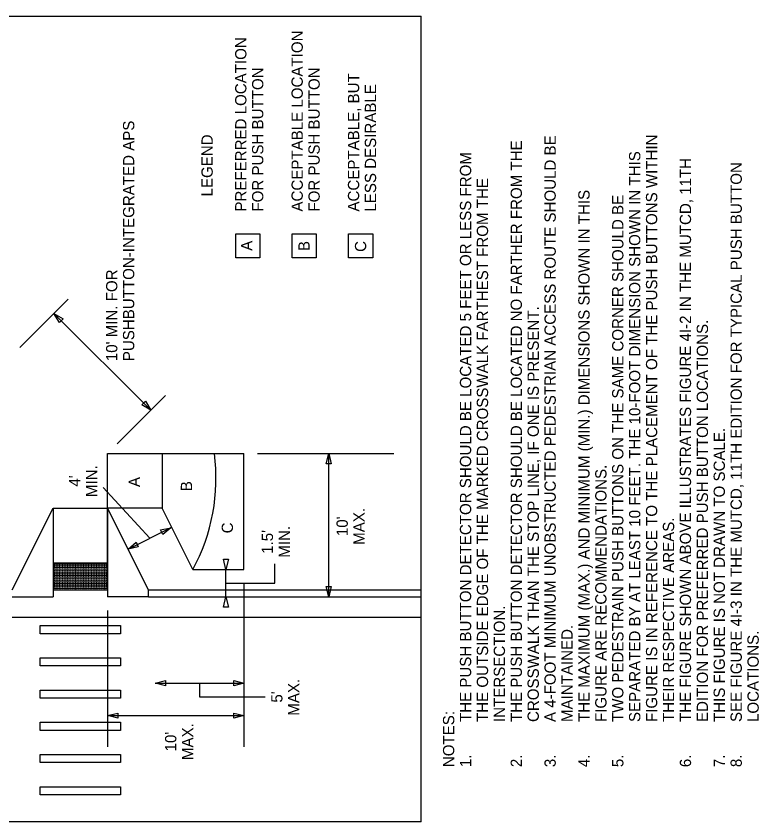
# Model space of a CAD drawing. Extents: x 610558 to 611161, y 419194 to 420064.
# Drawn here: x 610812 to 611088.7, y 419194 to 419494 of the extents above; entities that cross this region are included whole.
import ezdxf

# ---------------------------------------------------------------- set-up
doc = ezdxf.new("R2010")
doc.units = 0
doc.layers.add('Level 10', color=7, linetype='Continuous')

msp = doc.modelspace()

# ---------------------------------------------------------------- linework, layer by layer
at = {"layer": 'Level 10'}
for p, q in [((610673.08, 419494.01), (610962.92, 419494.01)), ((610962.92, 419194.01), (610962.92, 419494.01)), ((610813.45, 419370.66), (610831.4, 419388.61)), ((610826.14, 419383.35), (610862.24, 419347.26)), ((610849.73, 419334.74), (610867.68, 419352.7)), ((610866.43, 419331.13), (610896.9, 419331.13)), ((610896.9, 419287.96), (610896.9, 419331.13)), ((610901.98, 419331.13), (610952.77, 419331.13)), ((610928.49, 419277.81), (610928.49, 419331.13)), ((610861.86, 419299.65), (610844.51, 419318.55)), ((610810.56, 419280.35), (610825.8, 419310.82)), ((610825.8, 419310.82), (610846.11, 419310.82)), ((610825.8, 419310.82), (610825.8, 419280.35)), ((610825.8, 419310.82), (610825.8, 419277.81)), ((610846.11, 419280.35), (610846.11, 419310.82)), ((610861.35, 419280.35), (610846.11, 419310.82)), ((610846.11, 419310.82), (610846.11, 419277.81)), ((610877.86, 419287.96), (610866.43, 419310.82)), ((610853.73, 419295.58), (610869.98, 419303.71)), ((610825.8, 419290.5), (610846.11, 419290.5)), ((610877.86, 419287.96), (610896.9, 419287.96)), ((610890.19, 419277.81), (610890.19, 419287.96)), ((610825.8, 419280.35), (610846.11, 419280.35)), ((610861.35, 419277.81), (610861.35, 419280.35)), ((610861.35, 419280.35), (610962.92, 419280.35)), ((610896.9, 419282.89), (610896.9, 419221.94)), ((610810.56, 419277.81), (610825.8, 419277.81)), ((610861.35, 419277.81), (610846.11, 419277.81)), ((610861.35, 419277.81), (610962.92, 419277.81)), ((610846.11, 419272.73), (610846.11, 419221.94)), ((610810.56, 419270.19), (610861.35, 419270.19)), ((610861.35, 419270.19), (610962.92, 419270.19)), ((610863.89, 419245.65), (610896.9, 419245.65)), ((610846.11, 419233.56), (610896.9, 419233.56)), ((610962.92, 419194.01), (610673.08, 419194.01))]:
    msp.add_line(p, q, dxfattribs=at)
for points in [[(610893.85, 419403.96), (610893.85, 419412.96), (610902.85, 419412.96), (610902.85, 419403.96)], [(610914.85, 419403.96), (610914.85, 419412.96), (610923.85, 419412.96), (610923.85, 419403.96)], [(610935.85, 419403.96), (610935.85, 419412.96), (610944.85, 419412.96), (610944.85, 419403.96)], [(610828.16, 419379.99), (610826.14, 419383.35), (610829.51, 419381.33)], [(610860.22, 419350.63), (610862.24, 419347.26), (610858.87, 419349.28)], [(610846.11, 419310.82), (610846.11, 419331.13), (610866.43, 419331.13), (610866.43, 419310.82)], [(610927.54, 419327.32), (610928.49, 419331.13), (610929.44, 419327.32)], [(610865.82, 419302.69), (610869.65, 419303.54), (610866.67, 419300.99)], [(610857.56, 419296.43), (610853.73, 419295.58), (610856.71, 419298.14)], [(610891.14, 419291.77), (610890.19, 419287.96), (610889.24, 419291.77)], [(610929.44, 419281.62), (610928.49, 419277.81), (610927.54, 419281.62)], [(610889.24, 419274), (610890.19, 419277.81), (610891.14, 419274)], [(610820.96, 419264.08), (610820.96, 419267.08), (610850.96, 419267.08), (610850.96, 419264.08)], [(610820.96, 419252.08), (610820.96, 419255.08), (610850.96, 419255.08), (610850.96, 419252.08)], [(610867.7, 419244.7), (610863.89, 419245.65), (610867.7, 419246.61)], [(610893.09, 419246.61), (610896.9, 419245.65), (610893.09, 419244.7)], [(610820.96, 419240.08), (610820.96, 419243.08), (610850.96, 419243.08), (610850.96, 419240.08)], [(610849.92, 419232.61), (610846.11, 419233.56), (610849.92, 419234.51)], [(610893.09, 419234.51), (610896.9, 419233.56), (610893.09, 419232.61)], [(610820.96, 419228.08), (610820.96, 419231.08), (610850.96, 419231.08), (610850.96, 419228.08)], [(610820.96, 419216.08), (610820.96, 419219.08), (610850.96, 419219.08), (610850.96, 419216.08)], [(610820.96, 419204.08), (610820.96, 419207.08), (610850.96, 419207.08), (610850.96, 419204.08)]]:
    msp.add_lwpolyline(points, close=True, dxfattribs=at)
for points in [[(610890.19, 419282.89), (610908.43, 419282.89), (610908.43, 419290.07)], [(610880.39, 419245.65), (610880.39, 419240.57), (610904.82, 419240.57)]]:
    msp.add_lwpolyline(points, dxfattribs=at)
for centre in [(610826.36, 419289.95), (610826.36, 419289.35), (610826.96, 419289.95), (610826.96, 419289.35), (610827.56, 419289.95), (610827.56, 419289.35), (610828.16, 419289.95), (610828.16, 419289.35), (610828.76, 419289.95), (610828.76, 419289.35), (610829.36, 419289.95), (610829.36, 419289.35), (610829.96, 419289.95), (610829.96, 419289.35), (610830.56, 419289.95), (610830.56, 419289.35), (610831.16, 419289.95), (610831.16, 419289.35), (610831.76, 419289.95), (610831.76, 419289.35), (610832.36, 419289.95), (610832.36, 419289.35), (610832.96, 419289.95), (610832.96, 419289.35), (610833.56, 419289.95), (610833.56, 419289.35), (610834.16, 419289.95), (610834.16, 419289.35), (610834.76, 419289.95), (610834.76, 419289.35), (610835.36, 419289.95), (610835.36, 419289.35), (610835.96, 419289.95), (610835.96, 419289.35), (610836.56, 419289.95), (610836.56, 419289.35), (610837.16, 419289.95), (610837.16, 419289.35), (610837.76, 419289.95), (610837.76, 419289.35), (610838.36, 419289.95), (610838.36, 419289.35), (610838.96, 419289.95), (610838.96, 419289.35), (610839.56, 419289.95), (610839.56, 419289.35), (610840.16, 419289.95), (610840.16, 419289.35), (610840.76, 419289.95), (610840.76, 419289.35), (610841.36, 419289.95), (610841.36, 419289.35), (610841.96, 419289.95), (610841.96, 419289.35), (610842.56, 419289.95), (610842.56, 419289.35), (610843.16, 419289.95), (610843.16, 419289.35), (610843.76, 419289.95), (610843.76, 419289.35), (610844.36, 419289.95), (610844.36, 419289.35), (610844.96, 419289.95), (610844.96, 419289.35), (610845.56, 419289.95), (610845.56, 419289.35), (610826.36, 419288.75), (610826.36, 419288.15), (610826.36, 419287.55), (610826.36, 419286.95), (610826.36, 419286.35), (610826.96, 419288.75), (610826.96, 419288.15), (610826.96, 419287.55), (610826.96, 419286.95), (610826.96, 419286.35), (610827.56, 419288.75), (610827.56, 419288.15), (610827.56, 419287.55), (610827.56, 419286.95), (610827.56, 419286.35), (610828.16, 419288.75), (610828.16, 419288.15), (610828.16, 419287.55), (610828.16, 419286.95), (610828.16, 419286.35), (610828.76, 419288.75), (610828.76, 419288.15), (610828.76, 419287.55), (610828.76, 419286.95), (610828.76, 419286.35), (610829.36, 419288.75), (610829.36, 419288.15), (610829.36, 419287.55), (610829.36, 419286.95), (610829.36, 419286.35), (610829.96, 419288.75), (610829.96, 419288.15), (610829.96, 419287.55), (610829.96, 419286.95), (610829.96, 419286.35), (610830.56, 419288.75), (610830.56, 419288.15), (610830.56, 419287.55), (610830.56, 419286.95), (610830.56, 419286.35), (610831.16, 419288.75), (610831.16, 419288.15), (610831.16, 419287.55), (610831.16, 419286.95), (610831.16, 419286.35), (610831.76, 419288.75), (610831.76, 419288.15), (610831.76, 419287.55), (610831.76, 419286.95), (610831.76, 419286.35), (610832.36, 419288.75), (610832.36, 419288.15), (610832.36, 419287.55), (610832.36, 419286.95), (610832.36, 419286.35), (610832.96, 419288.75), (610832.96, 419288.15), (610832.96, 419287.55), (610832.96, 419286.95), (610832.96, 419286.35), (610833.56, 419288.75), (610833.56, 419288.15), (610833.56, 419287.55), (610833.56, 419286.95), (610833.56, 419286.35), (610834.16, 419288.75), (610834.16, 419288.15), (610834.16, 419287.55), (610834.16, 419286.95), (610834.16, 419286.35), (610834.76, 419288.75), (610834.76, 419288.15), (610834.76, 419287.55), (610834.76, 419286.95), (610834.76, 419286.35), (610835.36, 419288.75), (610835.36, 419288.15), (610835.36, 419287.55), (610835.36, 419286.95), (610835.36, 419286.35), (610835.96, 419288.75), (610835.96, 419288.15), (610835.96, 419287.55), (610835.96, 419286.95), (610835.96, 419286.35), (610836.56, 419288.75), (610836.56, 419288.15), (610836.56, 419287.55), (610836.56, 419286.95), (610836.56, 419286.35), (610837.16, 419288.75), (610837.16, 419288.15), (610837.16, 419287.55), (610837.16, 419286.95), (610837.16, 419286.35), (610837.76, 419288.75), (610837.76, 419288.15), (610837.76, 419287.55), (610837.76, 419286.95), (610837.76, 419286.35), (610838.36, 419288.75), (610838.36, 419288.15), (610838.36, 419287.55), (610838.36, 419286.95), (610838.36, 419286.35), (610838.96, 419288.75), (610838.96, 419288.15), (610838.96, 419287.55), (610838.96, 419286.95), (610838.96, 419286.35), (610839.56, 419288.75), (610839.56, 419288.15), (610839.56, 419287.55), (610839.56, 419286.95), (610839.56, 419286.35), (610840.16, 419288.75), (610840.16, 419288.15), (610840.16, 419287.55), (610840.16, 419286.95), (610840.16, 419286.35), (610840.76, 419288.75), (610840.76, 419288.15), (610840.76, 419287.55), (610840.76, 419286.95), (610840.76, 419286.35), (610841.36, 419288.75), (610841.36, 419288.15), (610841.36, 419287.55), (610841.36, 419286.95), (610841.36, 419286.35), (610841.96, 419288.75), (610841.96, 419288.15), (610841.96, 419287.55), (610841.96, 419286.95), (610841.96, 419286.35), (610842.56, 419288.75), (610842.56, 419288.15), (610842.56, 419287.55), (610842.56, 419286.95), (610842.56, 419286.35), (610843.16, 419288.75), (610843.16, 419288.15), (610843.16, 419287.55), (610843.16, 419286.95), (610843.16, 419286.35), (610843.76, 419288.75), (610843.76, 419288.15), (610843.76, 419287.55), (610843.76, 419286.95), (610843.76, 419286.35), (610844.36, 419288.75), (610844.36, 419288.15), (610844.36, 419287.55), (610844.36, 419286.95), (610844.36, 419286.35), (610844.96, 419288.75), (610844.96, 419288.15), (610844.96, 419287.55), (610844.96, 419286.95), (610844.96, 419286.35), (610845.56, 419288.75), (610845.56, 419288.15), (610845.56, 419287.55), (610845.56, 419286.95), (610845.56, 419286.35), (610826.36, 419285.75), (610826.36, 419285.15), (610826.36, 419284.55), (610826.36, 419283.95), (610826.36, 419283.35), (610826.96, 419285.75), (610826.96, 419285.15), (610826.96, 419284.55), (610826.96, 419283.95), (610826.96, 419283.35), (610827.56, 419285.75), (610827.56, 419285.15), (610827.56, 419284.55), (610827.56, 419283.95), (610827.56, 419283.35), (610828.16, 419285.75), (610828.16, 419285.15), (610828.16, 419284.55), (610828.16, 419283.95), (610828.16, 419283.35), (610828.76, 419285.75), (610828.76, 419285.15), (610828.76, 419284.55), (610828.76, 419283.95), (610828.76, 419283.35), (610829.36, 419285.75), (610829.36, 419285.15), (610829.36, 419284.55), (610829.36, 419283.95), (610829.36, 419283.35), (610829.96, 419285.75), (610829.96, 419285.15), (610829.96, 419284.55), (610829.96, 419283.95), (610829.96, 419283.35), (610830.56, 419285.75), (610830.56, 419285.15), (610830.56, 419284.55), (610830.56, 419283.95), (610830.56, 419283.35), (610831.16, 419285.75), (610831.16, 419285.15), (610831.16, 419284.55), (610831.16, 419283.95), (610831.16, 419283.35), (610831.76, 419285.75), (610831.76, 419285.15), (610831.76, 419284.55), (610831.76, 419283.95), (610831.76, 419283.35), (610832.36, 419285.75), (610832.36, 419285.15), (610832.36, 419284.55), (610832.36, 419283.95), (610832.36, 419283.35), (610832.96, 419285.75), (610832.96, 419285.15), (610832.96, 419284.55), (610832.96, 419283.95), (610832.96, 419283.35), (610833.56, 419285.75), (610833.56, 419285.15), (610833.56, 419284.55), (610833.56, 419283.95), (610833.56, 419283.35), (610834.16, 419285.75), (610834.16, 419285.15), (610834.16, 419284.55), (610834.16, 419283.95), (610834.16, 419283.35), (610834.76, 419285.75), (610834.76, 419285.15), (610834.76, 419284.55), (610834.76, 419283.95), (610834.76, 419283.35), (610835.36, 419285.75), (610835.36, 419285.15), (610835.36, 419284.55), (610835.36, 419283.95), (610835.36, 419283.35), (610835.96, 419285.75), (610835.96, 419285.15), (610835.96, 419284.55), (610835.96, 419283.95), (610835.96, 419283.35), (610836.56, 419285.75), (610836.56, 419285.15), (610836.56, 419284.55), (610836.56, 419283.95), (610836.56, 419283.35), (610837.16, 419285.75), (610837.16, 419285.15), (610837.16, 419284.55), (610837.16, 419283.95), (610837.16, 419283.35), (610837.76, 419285.75), (610837.76, 419285.15), (610837.76, 419284.55), (610837.76, 419283.95), (610837.76, 419283.35), (610838.36, 419285.75), (610838.36, 419285.15), (610838.36, 419284.55), (610838.36, 419283.95), (610838.36, 419283.35), (610838.96, 419285.75), (610838.96, 419285.15), (610838.96, 419284.55), (610838.96, 419283.95), (610838.96, 419283.35), (610839.56, 419285.75), (610839.56, 419285.15), (610839.56, 419284.55), (610839.56, 419283.95), (610839.56, 419283.35), (610840.16, 419285.75), (610840.16, 419285.15), (610840.16, 419284.55), (610840.16, 419283.95), (610840.16, 419283.35), (610840.76, 419285.75), (610840.76, 419285.15), (610840.76, 419284.55), (610840.76, 419283.95), (610840.76, 419283.35), (610841.36, 419285.75), (610841.36, 419285.15), (610841.36, 419284.55), (610841.36, 419283.95), (610841.36, 419283.35), (610841.96, 419285.75), (610841.96, 419285.15), (610841.96, 419284.55), (610841.96, 419283.95), (610841.96, 419283.35), (610842.56, 419285.75), (610842.56, 419285.15), (610842.56, 419284.55), (610842.56, 419283.95), (610842.56, 419283.35), (610843.16, 419285.75), (610843.16, 419285.15), (610843.16, 419284.55), (610843.16, 419283.95), (610843.16, 419283.35), (610843.76, 419285.75), (610843.76, 419285.15), (610843.76, 419284.55), (610843.76, 419283.95), (610843.76, 419283.35), (610844.36, 419285.75), (610844.36, 419285.15), (610844.36, 419284.55), (610844.36, 419283.95), (610844.36, 419283.35), (610844.96, 419285.75), (610844.96, 419285.15), (610844.96, 419284.55), (610844.96, 419283.95), (610844.96, 419283.35), (610845.56, 419285.75), (610845.56, 419285.15), (610845.56, 419284.55), (610845.56, 419283.95), (610845.56, 419283.35), (610826.36, 419282.75), (610826.36, 419282.15), (610826.36, 419281.55), (610826.36, 419280.95), (610826.96, 419282.75), (610826.96, 419282.15), (610826.96, 419281.55), (610826.96, 419280.95), (610827.56, 419282.75), (610827.56, 419282.15), (610827.56, 419281.55), (610827.56, 419280.95), (610828.16, 419282.75), (610828.16, 419282.15), (610828.16, 419281.55), (610828.16, 419280.95), (610828.76, 419282.75), (610828.76, 419282.15), (610828.76, 419281.55), (610828.76, 419280.95), (610829.36, 419282.75), (610829.36, 419282.15), (610829.36, 419281.55), (610829.36, 419280.95), (610829.96, 419282.75), (610829.96, 419282.15), (610829.96, 419281.55), (610829.96, 419280.95), (610830.56, 419282.75), (610830.56, 419282.15), (610830.56, 419281.55), (610830.56, 419280.95), (610831.16, 419282.75), (610831.16, 419282.15), (610831.16, 419281.55), (610831.16, 419280.95), (610831.76, 419282.75), (610831.76, 419282.15), (610831.76, 419281.55), (610831.76, 419280.95), (610832.36, 419282.75), (610832.36, 419282.15), (610832.36, 419281.55), (610832.36, 419280.95), (610832.96, 419282.75), (610832.96, 419282.15), (610832.96, 419281.55), (610832.96, 419280.95), (610833.56, 419282.75), (610833.56, 419282.15), (610833.56, 419281.55), (610833.56, 419280.95), (610834.16, 419282.75), (610834.16, 419282.15), (610834.16, 419281.55), (610834.16, 419280.95), (610834.76, 419282.75), (610834.76, 419282.15), (610834.76, 419281.55), (610834.76, 419280.95), (610835.36, 419282.75), (610835.36, 419282.15), (610835.36, 419281.55), (610835.36, 419280.95), (610835.96, 419282.75), (610835.96, 419282.15), (610835.96, 419281.55), (610835.96, 419280.95), (610836.56, 419282.75), (610836.56, 419282.15), (610836.56, 419281.55), (610836.56, 419280.95), (610837.16, 419282.75), (610837.16, 419282.15), (610837.16, 419281.55), (610837.16, 419280.95), (610837.76, 419282.75), (610837.76, 419282.15), (610837.76, 419281.55), (610837.76, 419280.95), (610838.36, 419282.75), (610838.36, 419282.15), (610838.36, 419281.55), (610838.36, 419280.95), (610838.96, 419282.75), (610838.96, 419282.15), (610838.96, 419281.55), (610838.96, 419280.95), (610839.56, 419282.75), (610839.56, 419282.15), (610839.56, 419281.55), (610839.56, 419280.95), (610840.16, 419282.75), (610840.16, 419282.15), (610840.16, 419281.55), (610840.16, 419280.95), (610840.76, 419282.75), (610840.76, 419282.15), (610840.76, 419281.55), (610840.76, 419280.95), (610841.36, 419282.75), (610841.36, 419282.15), (610841.36, 419281.55), (610841.36, 419280.95), (610841.96, 419282.75), (610841.96, 419282.15), (610841.96, 419281.55), (610841.96, 419280.95), (610842.56, 419282.75), (610842.56, 419282.15), (610842.56, 419281.55), (610842.56, 419280.95), (610843.16, 419282.75), (610843.16, 419282.15), (610843.16, 419281.55), (610843.16, 419280.95), (610843.76, 419282.75), (610843.76, 419282.15), (610843.76, 419281.55), (610843.76, 419280.95), (610844.36, 419282.75), (610844.36, 419282.15), (610844.36, 419281.55), (610844.36, 419280.95), (610844.96, 419282.75), (610844.96, 419282.15), (610844.96, 419281.55), (610844.96, 419280.95), (610845.56, 419282.75), (610845.56, 419282.15), (610845.56, 419281.55), (610845.56, 419280.95)]:
    msp.add_circle(centre, 0.112, dxfattribs=at)
msp.add_arc((610815.42, 419321.92), 71.07, 331.4599, 7.446, dxfattribs=at)

# ---------------------------------------------------------------- texts
for s, p in [('ACCEPTABLE LOCATION ', (610918.82, 419421.24)), ('PREFERRED LOCATION ', (610897.82, 419421.24)), ('FOR PUSH BUTTON', (610904.12, 419421.24)), ('FOR PUSH BUTTON', (610925.12, 419421.24)), ('ACCEPTABLE, BUT ', (610939.82, 419421.24)), ('LESS DESIRABLE', (610946.12, 419421.24)), ('PUSHBUTTON-INTEGRATED APS', (610856.05, 419365.54)), ('LEGEND', (610885.27, 419426.87)), ('A 4-FOOT MINIMUM UNOBSTRUCTED PEDESTRIAN ACCESS ROUTE SHOULD BE ', (611013.03, 419231.19)), ('FIGURE IS IN REFERENCE TO THE PLACEMENT OF THE PUSH BUTTONS WITHIN ', (611050.83, 419231.19)), ('THE PUSH BUTTON DETECTOR SHOULD BE LOCATED NO FARTHER FROM THE ', (611000.43, 419231.19)), ('THE PUSH BUTTON DETECTOR SHOULD BE LOCATED 5 FEET OR LESS FROM ', (610981.53, 419231.19)), ('SEPARATED BY AT LEAST 10 FEET. THE 10-FOOT DIMENSION SHOWN IN THIS ', (611044.53, 419231.19)), ('THE FIGURE SHOWN ABOVE ILLUSTRATES FIGURE 4I-2 IN THE MUTCD, 11TH ', (611063.43, 419231.19)), ('SEE FIGURE 4I-3 IN THE MUTCD, 11TH EDITION FOR TYPICAL PUSH BUTTON ', (611082.33, 419231.19)), ('THE OUTSIDE EDGE OF THE MARKED CROSSWALK FARTHEST FROM THE ', (610987.83, 419231.19)), ('THE MAXIMUM (MAX.) AND MINIMUM (MIN.) DIMENSIONS SHOWN IN THIS ', (611025.63, 419231.19)), ('TWO PEDESTRAIN PUSH BUTTONS ON THE SAME CORNER SHOULD BE ', (611038.23, 419231.19)), ('A', (610900.01, 419406.65)), ('B', (610921.38, 419406.54)), ('C', (610942.44, 419406.22)), ("10' MIN. FOR ", (610849.75, 419365.54)), ('CROSSWALK THAN THE STOP LINE, IF ONE IS PRESENT.', (611006.73, 419231.19)), ('EDITION FOR PREFERRED PUSH BUTTON LOCATIONS.', (611069.73, 419231.19)), ('THIS FIGURE IS NOT DRAWN TO SCALE.', (611076.03, 419231.19)), ('MIN.', (610842.26, 419314.94)), ('FIGURE ARE RECOMMENDATIONS.', (611031.93, 419231.19)), ("4'", (610835.96, 419318.83)), ('A', (610858.17, 419318.67)), ('B', (610877.58, 419317.14)), ('MAX.', (610941.87, 419297.16)), ("10'", (610935.57, 419300.4)), ('C', (610892.81, 419301.44)), ('THEIR RESPECTIVE AREAS.', (611057.13, 419231.19)), ("1.5'", (610907.72, 419293.81)), ('MIN.', (610914.02, 419292.37)), ('INTERSECTION.', (610994.13, 419231.19)), ('MAINTAINED.', (611019.33, 419231.19)), ('LOCATIONS.', (611088.63, 419231.19)), ('MAX.', (610917.54, 419233.55)), ("5'", (610911.24, 419238.42)), ('NOTES:', (610975.23, 419214.39)), ('MAX.', (610878.02, 419217.01)), ("10'", (610871.72, 419220.24)), ('1.', (610981.53, 419214.39)), ('2.', (611000.43, 419214.39)), ('3.', (611013.03, 419214.39)), ('4.', (611025.63, 419214.39)), ('5.', (611038.23, 419214.39)), ('6.', (611063.43, 419214.39)), ('7.', (611076.03, 419214.39)), ('8.', (611082.33, 419214.39))]:
    msp.add_text(s, height=4.2, rotation=90, dxfattribs=at).set_placement(p)

doc.saveas('drawing.dxf')
